// Mitsubishi GX Works2 project: 45.8个彩灯3种模式循环   PLC: FX3U/FX3UC

PROGRAM MAIN
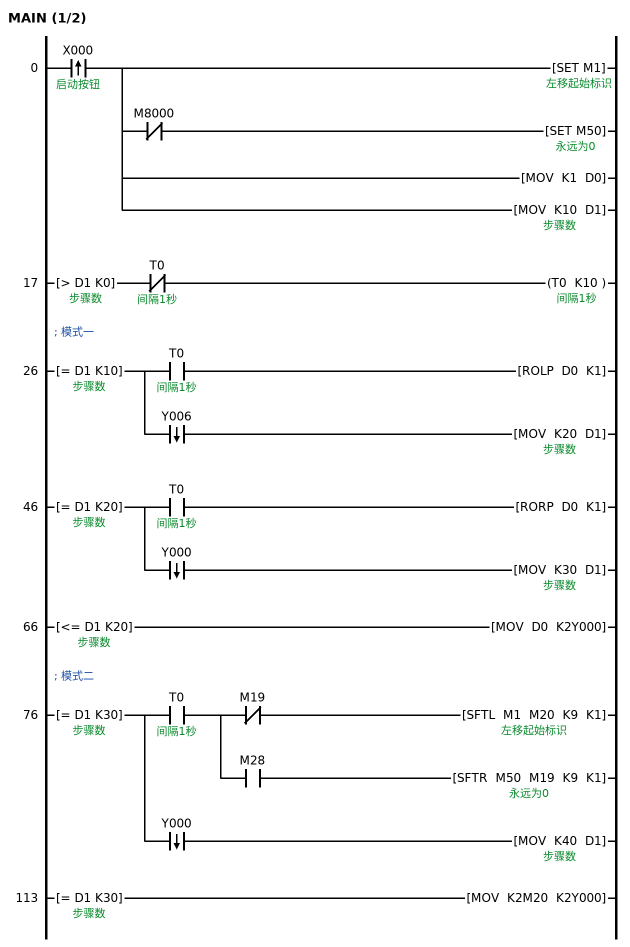
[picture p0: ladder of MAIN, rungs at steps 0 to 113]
0     LDP     X000  ; 启动按钮
      SET     M1  ; 左移起始标识
      MPS
      ANI     M8000
      SET     M50  ; 永远为0
      MPP
      MOV     K1 D0
      MOV     K10 D1  ; 步骤数
17    LD>     D1 K0  ; 步骤数
      ANI     T0  ; 间隔1秒
      OUT     T0 K10  ; 间隔1秒
; 模式一
26    LD=     D1 K10  ; 步骤数
      MPS
      AND     T0  ; 间隔1秒
      ROLP    D0 K1
        [note] 左循环：顺序逐个点亮
      MPP
      ANDF    Y006
      MOV     K20 D1
46    LD=     D1 K20  ; 步骤数
      MPS
      AND     T0  ; 间隔1秒
      RORP    D0 K1
        [note] 右循环：逆序逐个点亮
      MPP
      ANDF    Y000
      MOV     K30 D1
66    LD<=    D1 K20  ; 步骤数
      MOV     D0 K2Y000
; 模式二
76    LD=     D1 K30  ; 步骤数
      MPS
      AND     T0  ; 间隔1秒
      MPS
      ANI     M19
      SFTL    M1 M20 K9 K1
      MPP
      AND     M28
      SFTR    M50 M19 K9 K1
      MPP
      ANDF    Y000
      MOV     K40 D1
113   LD=     D1 K30  ; 步骤数
      MOV     K2M20 K2Y000
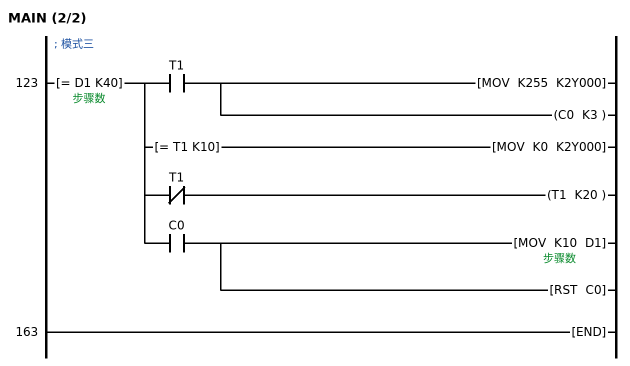
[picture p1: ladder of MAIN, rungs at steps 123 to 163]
; 模式三
123   LD=     D1 K40  ; 步骤数
      MPS
      AND     T1
      MOV     K255 K2Y000
        [note] 亮2秒，中间灭1秒
      OUT     C0 K3
      MRD
      AND=    T1 K10
      MOV     K0 K2Y000
      MRD
      ANI     T1
      OUT     T1 K20
      MPP
      AND     C0
      MOV     K10 D1
        [note] 回到模式一
      RST     C0
163   END
END_PROGRAM

// device comments not shown above
M0  ; 运行标识
